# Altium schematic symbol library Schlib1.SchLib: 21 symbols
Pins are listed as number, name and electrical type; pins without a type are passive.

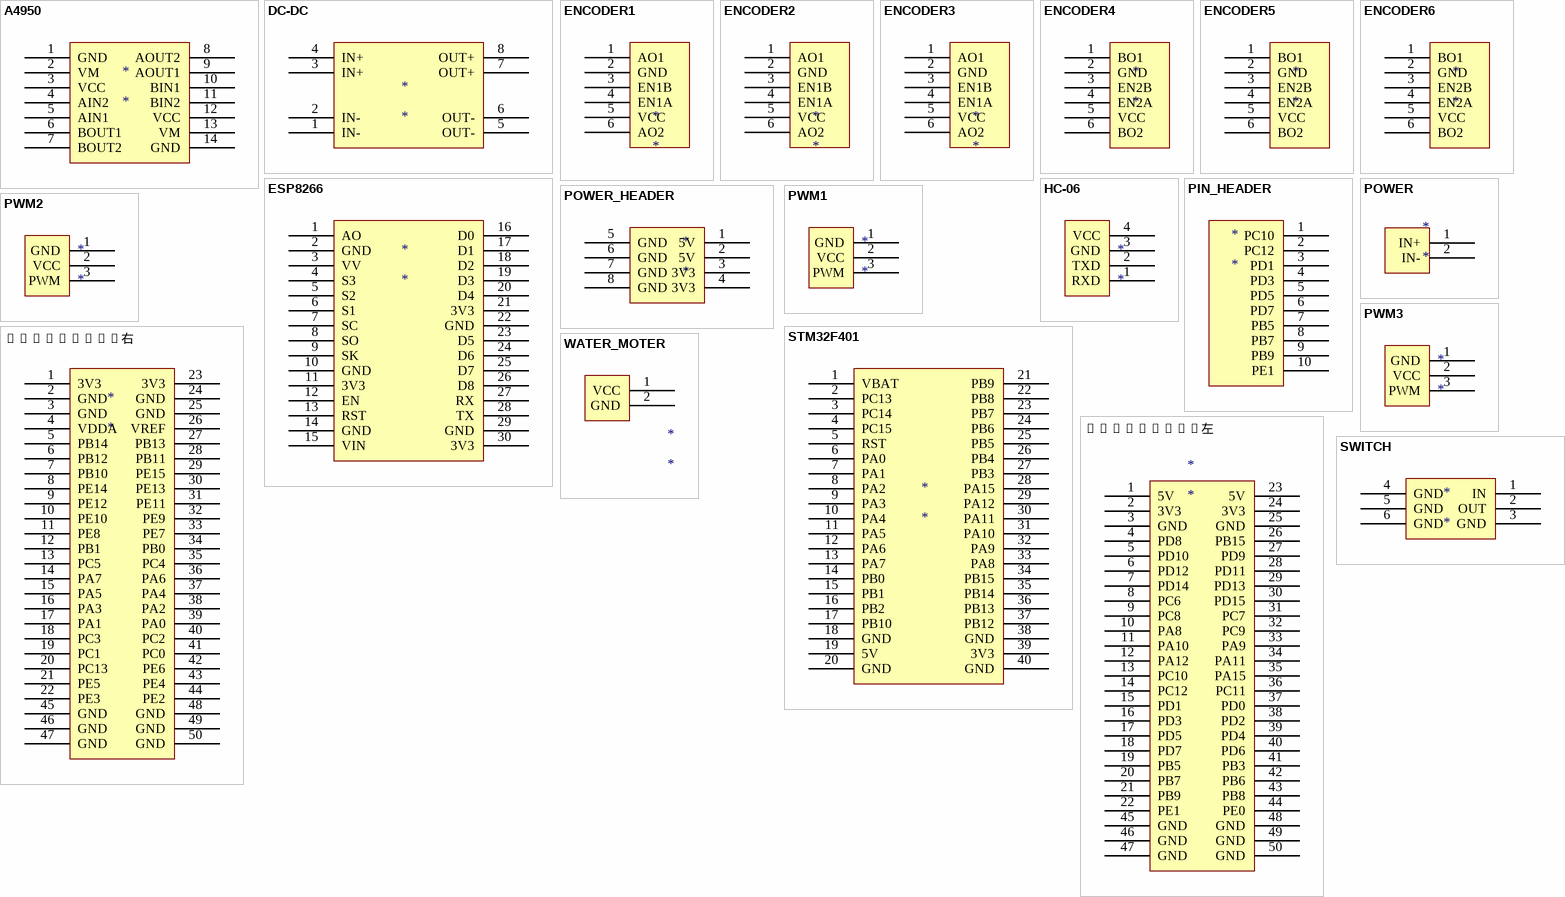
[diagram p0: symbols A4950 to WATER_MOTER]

## A4950
designator *
footprint A4950
pins: 1 GND, 2 VM, 3 VCC, 4 AIN2, 5 AIN1, 6 BOUT1, 7 BOUT2, 8 AOUT2, 9 AOUT1, 10 BIN1, 11 BIN2, 12 VCC, 13 VM, 14 GND

## DC-DC
designator *
footprint DC-DC
pins: 1 IN-, 2 IN-, 3 IN+, 4 IN+, 5 OUT-, 6 OUT-, 7 OUT+, 8 OUT+

## ENCODER1
designator *
footprint ENCODER1
footprint ENCODER1
pins: 1 AO1, 2 GND, 3 EN1B, 4 EN1A, 5 VCC, 6 AO2

## ENCODER2
designator *
footprint ENCODER1
pins: 1 AO1, 2 GND, 3 EN1B, 4 EN1A, 5 VCC, 6 AO2

## ENCODER3
designator *
footprint ENCODER1
pins: 1 AO1, 2 GND, 3 EN1B, 4 EN1A, 5 VCC, 6 AO2

## ENCODER4
designator *
footprint ENCODER2
pins: 1 BO1, 2 GND, 3 EN2B, 4 EN2A, 5 VCC, 6 BO2

## ENCODER5
designator *
footprint ENCODER2
pins: 1 BO1, 2 GND, 3 EN2B, 4 EN2A, 5 VCC, 6 BO2

## ENCODER6
designator *
footprint ENCODER2
pins: 1 BO1, 2 GND, 3 EN2B, 4 EN2A, 5 VCC, 6 BO2

## ESP8266
designator *
footprint ESP
pins: 1 AO, 2 GND, 3 VV, 4 S3, 5 S2, 6 S1, 7 SC, 8 SO, 9 SK, 10 GND, 11 3V3, 12 EN, 13 RST, 14 GND, 15 VIN, 16 D0, 17 D1, 18 D2, 19 D3, 20 D4, 21 3V3, 22 GND, 23 D5, 24 D6, 25 D7, 26 D8, 27 RX, 28 TX, 29 GND, 30 3V3

## HC-06
designator *
footprint HC-06
pins: 1 RXD, 2 TXD, 3 GND, 4 VCC

## PIN_HEADER
designator *
footprint PIN_HEADER
pins: 1 PC10, 2 PC12, 3 PD1, 4 PD3, 5 PD5, 6 PD7, 7 PB5, 8 PB7, 9 PB9, 10 PE1

## POWER
designator *
footprint POWER
pins: 1 IN+, 2 IN-

## POWER_HEADER
designator *
footprint POWER_HEADER
footprint POWER_HEADER
pins: 1 5V, 2 5V, 3 3V3, 4 3V3, 5 GND, 6 GND, 7 GND, 8 GND

## PWM1
designator *
footprint PWM
pins: 1 GND, 2 VCC, 3 PWM

## PWM2
designator *
footprint PWM
pins: 1 GND, 2 VCC, 3 PWM

## PWM3
designator *
footprint PWM
pins: 1 GND, 2 VCC, 3 PWM

## STM32F401
designator *
footprint STM32F401CCU6
pins: 1 VBAT, 2 PC13, 3 PC14, 4 PC15, 5 RST, 6 PA0, 7 PA1, 8 PA2, 9 PA3, 10 PA4, 11 PA5, 12 PA6, 13 PA7, 14 PB0, 15 PB1, 16 PB2, 17 PB10, 18 GND, 19 5V, 20 GND, 21 PB9, 22 PB8, 23 PB7, 24 PB6, 25 PB5, 26 PB4, 27 PB3, 28 PA15, 29 PA12, 30 PA11, 31 PA10, 32 PA9, 33 PA8, 34 PB15, 35 PB14, 36 PB13, 37 PB12, 38 GND, 39 3V3, 40 GND

## STM32F407右
designator *
footprint STM32F407左
pins: 1 3V3, 2 GND, 3 GND, 4 VDDA, 5 PB14, 6 PB12, 7 PB10, 8 PE14, 9 PE12, 10 PE10, 11 PE8, 12 PB1, 13 PC5, 14 PA7, 15 PA5, 16 PA3, 17 PA1, 18 PC3, 19 PC1, 20 PC13, 21 PE5, 22 PE3, 23 3V3, 24 GND, 25 GND, 26 VREF, 27 PB13, 28 PB11, 29 PE15, 30 PE13, 31 PE11, 32 PE9, 33 PE7, 34 PB0, 35 PC4, 36 PA6, 37 PA4, 38 PA2, 39 PA0, 40 PC2, 41 PC0, 42 PE6, 43 PE4, 44 PE2, 45 GND, 46 GND, 47 GND, 48 GND, 49 GND, 50 GND

## STM32F407左
designator *
footprint STM32F407左
pins: 1 5V, 2 3V3, 3 GND, 4 PD8, 5 PD10, 6 PD12, 7 PD14, 8 PC6, 9 PC8, 10 PA8, 11 PA10, 12 PA12, 13 PC10, 14 PC12, 15 PD1, 16 PD3, 17 PD5, 18 PD7, 19 PB5, 20 PB7, 21 PB9, 22 PE1, 23 5V, 24 3V3, 25 GND, 26 PB15, 27 PD9, 28 PD11, 29 PD13, 30 PD15, 31 PC7, 32 PC9, 33 PA9, 34 PA11, 35 PA15, 36 PC11, 37 PD0, 38 PD2, 39 PD4, 40 PD6, 41 PB3, 42 PB6, 43 PB8, 44 PE0, 45 GND, 46 GND, 47 GND, 48 GND, 49 GND, 50 GND

## SWITCH
designator *
footprint SIWITCH
pins: 1 IN, 2 OUT, 3 GND, 4 GND, 5 GND, 6 GND

## WATER_MOTER
designator *
footprint WATER_HEADER
pins: 1 VCC, 2 GND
